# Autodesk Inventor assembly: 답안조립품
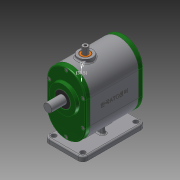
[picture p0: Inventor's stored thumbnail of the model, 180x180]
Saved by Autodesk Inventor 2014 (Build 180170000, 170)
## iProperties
Created: 2016-12
Part Number: 답안조립품
Document SubType Name: Assembly
Designer: user
Author: user
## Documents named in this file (14)
- C:\Users\user\Desktop\361208V1006\답안조립품.iam
- C:\Users\user\Desktop\361208V1006\본체.ipt
- C:\Users\user\Desktop\361208V1006\앞커버.ipt
- C:\Users\user\Desktop\361208V1006\뒤커버.ipt
- C:\Users\user\Desktop\361208V1006\베어링 6003.ipt
- C:\Users\user\Desktop\361208V1006\베어링 608.ipt
- C:\Users\user\Desktop\361208V1006\오일실 17 32 8.ipt
- C:\Users\user\Desktop\361208V1006\오일실 8 22 7.ipt
- C:\Users\user\Desktop\361208V1006\서브축.ipt
- C:\Users\user\Desktop\361208V1006\메인축.ipt
- C:\Users\user\Desktop\361208V1006\부시.ipt
- C:\Users\user\Desktop\361208V1006\슬라이더.ipt
- C:\Users\user\Desktop\361208V1006\가변스프링.ipt
- C:\Users\user\Desktop\361208V1006\볼트 M4.ipt
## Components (1 placed, 1 different names)
1. 가변스프링:1 — Mate:2, Mate:3, Mate:4
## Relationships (3: Mate 3)
- Mate:2: 가변스프링:1
- Mate:3: 가변스프링:1
- Mate:4: 가변스프링:1
